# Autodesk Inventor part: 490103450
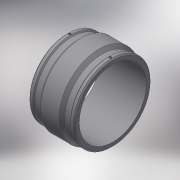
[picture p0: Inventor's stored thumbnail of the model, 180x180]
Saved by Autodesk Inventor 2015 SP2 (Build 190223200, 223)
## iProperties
Created: 2017-06
Part Number: 490103450
Material: Generic
Description: PLASSON COUPLER 450
Document SubType Name: Modeling
Designer: KIM
Mass: 16397.3 g
Surface Area: 10536.7 cm^2
Volume: 16397.3 cm^3
Density: 1 g/cm^3
Appearance: Default
Author: KIM
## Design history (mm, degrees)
derived "490103.ipt"
feature "Solid1::490103.ipt"
tag "TaggingFeature1"
body "Solid1"
other parameters: "d13" = 306, "d15" = 153, "d16" = 153, "d22" = 514, "d23" = 539, "d24" = 498.58, "d25" = 135 deg, "d26" = 122.4, "d27" = 135 deg, "d29" = 257, "d35" = 15, "d39" = 0, "d40" = 4, "d41" = 14, "d42" = 0, "d43" = 135 deg, "d44" = 33.66, "d46" = 6, "d47" = 0, "L_" = 306, "L_1" = 153, "D_" = 539, "A_" = 257, "d_2" = 12
